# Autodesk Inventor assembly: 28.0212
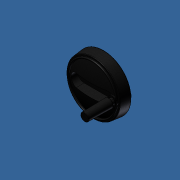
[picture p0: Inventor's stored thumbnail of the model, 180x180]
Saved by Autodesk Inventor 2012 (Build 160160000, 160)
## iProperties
Created: 2011-09
Part Number: 28.0212
Document SubType Name: Assembly
Designer: Administrator
Description: MINI ADJ UNIT HANDWHEEL
Vendor: S
Author: Administrator
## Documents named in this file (3)
- C:\Andys Backup Data\ANDY'S INVENTOR\INVENTOR LIBRARIES\PARTS LIBRARY\READY FOR USE MODULES LG\SUBCOMPONENTS\28.0212 HANDWHEEL 80mm.iam
- C:\Andys Backup Data\ANDY'S INVENTOR\INVENTOR LIBRARIES\PARTS LIBRARY\READY FOR USE MODULES LG\SUBCOMPONENTS\28.0212_1 MINI ADJ HANDWHEEL.ipt
- C:\Andys Backup Data\ANDY'S INVENTOR\INVENTOR LIBRARIES\PARTS LIBRARY\FASTENING ELEMENTS\SET SCREWS\21.1314 M4x8 SET SCREW POINTED.IPT
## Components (2 placed, 2 different names)
1. 28.0212_1 MINI ADJ HANDWHEEL:1 — Flush:1, Mate:1, Flush:2, Mate:2
2. 21.1314 M4X8 SET SCREW CONE POINT DIN 914:1 — Mate:2, Mate:3
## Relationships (5: Mate 3, Flush 2)
- Flush:1: 28.0212_1 MINI ADJ HANDWHEEL:1
- Mate:1: 28.0212_1 MINI ADJ HANDWHEEL:1
- Flush:2: 28.0212_1 MINI ADJ HANDWHEEL:1
- Mate:2: 28.0212_1 MINI ADJ HANDWHEEL:1 ↔ 21.1314 M4X8 SET SCREW CONE POINT DIN 914:1
- Mate:3: 21.1314 M4X8 SET SCREW CONE POINT DIN 914:1
